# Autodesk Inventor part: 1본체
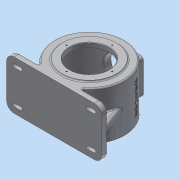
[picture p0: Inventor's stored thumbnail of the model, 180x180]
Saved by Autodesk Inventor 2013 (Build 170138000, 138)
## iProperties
Created: 2015-06
Part Number: 1본체
Material: 알루미늄 6061
Document SubType Name: Modeling
Designer: dgall
Density: 1 g/cm^3
Author: dgall
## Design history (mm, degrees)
sketch "스케치1"
  geometry: C1 r 85 at (0, 0); 1 further point
  constraints: 1 centre point, 1 coincident
  dimensions: "d0" = 170 diameter of C1
extrude "돌출1" new body sketch "스케치1" stored distance "d1" = 118; taper "d2" = 0 deg
sketch "스케치2"
  geometry: C1 r 77 at (0, 0); 1 further point
  constraints: 1 centre point, 1 coincident
  dimensions: "d3" = 154 diameter of C1
extrude "돌출2" cut sketch "스케치2" stored distance "d4" = 102; taper "d5" = 0 deg
sketch "스케치3"
  geometry: C1 r 85 at (0, 0) reference; C2 r 65 at (0, 0)
  constraints: 1 centre point, 1 coincident
  dimensions: "d6" = 130 diameter of C2
extrude "돌출3" join sketch "스케치3" distance "d7" = 3; taper "d8" = 0 deg
hole "구멍1" diameter "d11" = 95; stored, may be unused: countersink angle "d15" = 90 deg, drill point angle "d17" = 0 deg; dims "d9" = 10, "d10" = 10, "d12" = 6, "d13" = 4, "d14" = 2, "d16" = 11
sketch "스케치4"
  geometry: C1 r 85 at (0, 0) reference; C2 r 65 at (0, 0)
  constraints: 1 centre point, 1 coincident
  dimensions: "d18" = 130 diameter of C2
extrude "돌출4" join sketch "스케치4" distance "d19" = 13; taper "d20" = 0 deg
sketch "스케치5"
  geometry: C1 r 77 at (0, 0) reference; C2 r 31 at (0, 0)
  constraints: 1 centre point, 1 coincident
  dimensions: "d21" = 62 diameter of C2
extrude "돌출5" join sketch "스케치5" distance "d22" = 3.5; taper "d23" = -25 deg
hole "구멍2" diameter "d26" = 30; stored, may be unused: countersink angle "d30" = 90 deg, drill point angle "d32" = 0 deg; dims "d24" = 10, "d25" = 10, "d27" = 6, "d28" = 47, "d29" = 14, "d31" = 17
fillet "모깎기1" dims "d33" = 0.3
sketch "스케치6"
  geometry: L1 (115, -71)-(115, -85); L2 (115, -85)-(-115, -85); L3 (-115, -85)-(-115, -71); L4 (-115, -71)-(-29.799, -71); L5 (29.799, -71)-(115, -71); C1 r 31 at (0, 0) reference; C2 r 77 at (0, 0) reference; A1 r 77 centre (0, 0) between (-29.799, -71) and (29.799, -71); 2 further points
  constraints: 10 end point, 3 parallel, 2 horizontal, 2 perpendicular, 2 point on circle, 1 centre point, 1 coincident, 1 collinear, 1 concentric, 1 midpoint, 1 vertical alignment
  dimensions: "d34" = 14 distance of L2.end L3.end; "d36" = 85 distance from line of point (0, 0) L2; "d37" = 230 distance of L1.end L2.end
extrude "돌출6" join sketch "스케치6" stored distance "d38" = 118; taper "d39" = 0 deg
node "작업 평면1"
sketch "스케치7"
  geometry: L1 (-157.5, -16.5)-(-72.5, -16.5); L2 (-72.5, -16.5)-(-72.5, -101.5); L3 (-72.5, -101.5)-(-157.5, -101.5); L4 (-157.5, -101.5)-(-157.5, -16.5); 3 further points
  constraints: 8 end point, 2 midpoint, 2 parallel, 2 perpendicular, 1 horizontal, 1 horizontal alignment, 1 vertical alignment
  dimensions: "d41" = 85 distance of L1.start L1.end
extrude "돌출7" join sketch "스케치7" stored distance "d43" = 118; taper "d44" = 0 deg
hole "구멍3" diameter "d47" = 70; stored, may be unused: countersink angle "d51" = 90 deg, drill point angle "d53" = 0 deg; dims "d45" = 42.5, "d46" = 42.5, "d48" = 6, "d49" = 47, "d50" = 14, "d52" = 17
fillet "모깎기2" dims "d54" = 7
fillet "모깎기3" dims "d55" = 3
fillet "모깎기4" dims "d56" = 3
sketch "스케치8"
  geometry: L1 (-115, -71)-(-55.857, -71) reference; L2 (-109, -71)-(-84.87, -4.703); L3 (-115, -85)-(-115, -71) reference; A1 r 85 centre (0, 0) between (53.953, -65.682) and (-53.953, -65.682) reference; A2 r 3 centre (-55.857, -68) between (-55.857, -71) and (-53.953, -65.682) reference; 1 further point
  constraints: 2 end point, 1 point on circle, 1 point on line
  dimensions: "d57" = 6 distance from line of L2.start L3; "d58" = 110 deg angle of L1 L2
feature "리브1" sketch "스케치8" dims "d59" = 1, "d60" = 15, "d61" = 0, "d62" = 0, "d63" = 1, "d64" = 1
chamfer "모따기1" distance "d65" = 1; stored, may be unused: second distance "d66" = 2, angle "d67" = 45 deg
fillet "모깎기5" dims "d68" = 3
fillet "모깎기6" dims "d69" = 3
fillet "모깎기7" dims "d70" = 18
node "작업 평면2"
sketch "스케치9"
  geometry: L1 (53.143, -51.5)-(12, -51.5) reference; L2 (53.143, 0)-(53.143, -51.5) reference; L3 (53.143, 0)-(0, 0) reference; L4 (0, 0)-(0, 15) reference; L5 (0, 15)-(53.143, 15) reference; L6 (53.143, 66.5)-(53.143, 15) reference; L7 (12, 66.5)-(53.143, 66.5) reference; L8 (-6, -33.5)-(-6, 48.5) reference; L9 (12, 57.5)-(28, 57.5); L10 (28, 39.5)-(12, 39.5); L11 (28, 52.5)-(12, 52.5); L12 (12, 44.5)-(28, 44.5); A1 r 18 centre (12, -33.5) between (-6, -33.5) and (12, -51.5) reference; A2 r 18 centre (12, 48.5) between (12, 66.5) and (-6, 48.5) reference; A3 r 9 centre (12, 48.5) between (12, 57.5) and (12, 39.5); A4 r 9 centre (28, 48.5) between (28, 39.5) and (28, 57.5); A5 r 4 centre (12, 48.5) between (12, 52.5) and (12, 44.5); A6 r 4 centre (28, 48.5) between (28, 44.5) and (28, 52.5); 1 further point
  constraints: 8 end point, 8 point on circle, 4 centre point, 4 tangent, 1 coincident, 1 horizontal alignment, 3 other
  dimensions: "d72" = 18 diameter of A3; "d74" = 18 diameter of A4; "d75" = 16 distance of L9.start L9.end; "d76" = 5 distance between parallel lines of L9 L11
  node "투영된 루프2"
extrude "돌출8" join sketch "스케치9" stored distance "d77" = 118; taper "d78" = 0 deg
extrude "돌출9" cut sketch "스케치9" stored distance "d79" = 118; taper "d80" = 0 deg
fillet "모깎기8" dims "d81" = 3
fillet "모깎기9" dims "d82" = 7.5
fillet "모깎기10" dims "d83" = 3
fillet "모깎기11" dims "d85" = 3
fillet "모깎기12" dims "d86" = 3
fillet "모깎기13" dims "d87" = 3
sketch "스케치10"
  geometry: C1 r 65 at (0, 0) reference; 1 further point
  constraints: 1 vertical alignment
  dimensions: "d88" = 55 distance of C1.centre point (0, 55)
hole "구멍4" sketch "스케치10" at (0, 55) diameter "d89" = 3.242; stored, may be unused: countersink angle "d93" = 90 deg, drill point angle "d95" = 118 deg; dims "d90" = 6, "d91" = 47, "d92" = 14, "d94" = 17
sketch "스케치11"
  geometry: A1 r 7 centre (79.5, 23.5) between (72.5, 23.5) and (79.5, 16.5) reference; A2 r 7 centre (150.5, 23.5) between (150.5, 16.5) and (157.5, 23.5) reference; A3 r 7 centre (150.5, 94.5) between (157.5, 94.5) and (150.5, 101.5) reference; A4 r 7 centre (79.5, 94.5) between (79.5, 101.5) and (72.5, 94.5) reference; 4 further points
  constraints: 4 coincident
hole "구멍5" sketch "스케치11" at (79.5, 23.5), (150.5, 23.5), (150.5, 94.5), (79.5, 94.5) diameter "d99" = 3.242; stored, may be unused: countersink angle "d103" = 90 deg, drill point angle "d105" = 118 deg; dims "d100" = 10, "d101" = 47, "d102" = 14, "d104" = 13
chamfer "모따기2" distance "d110" = 1; stored, may be unused: second distance "d111" = 2, angle "d112" = 45 deg
node "작업 평면10"
  node "작업 평면9"
sketch "스케치13"
  geometry: 2 further points
  constraints: 1 coincident, 1 other
feature "엠보싱2" sketch "스케치13" dims "d114" = 0.5, "d115" = 0
fillet "모깎기14" dims "d116" = 3
node "솔리드1"
mirror "대칭1"
mirror "대칭2"
mirror "대칭3"
pattern_circular "원형 패턴1" dims angle "d97" = 360 deg
node "투영된 루프1"
node "작업축3"
other parameters: "d40" = -173, "d71" = 3, "d113" = 25 deg
